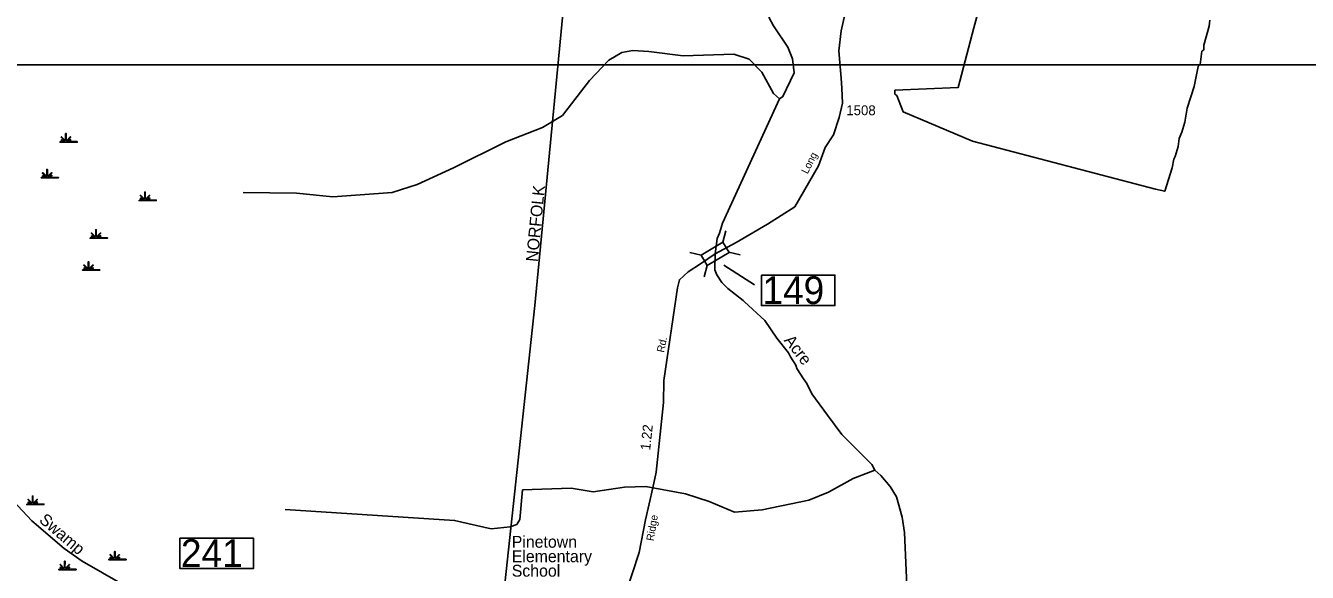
# Model space of a CAD drawing. Extents: x 2532689 to 2764727, y 536648 to 732970.
# Drawn here: x 2628920 to 2645127, y 685924 to 692837 of the extents above; entities that cross this region are included whole.
import ezdxf

# ---------------------------------------------------------------- set-up
doc = ezdxf.new("R2010")
doc.units = 0
for name, color, linetype in [('Exist Cultural Educational Facility Elementary Label', 7, 'Continuous'), ('Exist Hydrographic Creek Single Shore', 7, 'Continuous'), ('Exist Hydrographic Creek Single Shore Label', 7, 'Continuous'), ('Exist Hydrographic Swamp CELL', 7, 'Continuous'), ('Exist Railroad Mainline', 7, 'Continuous'), ('Exist Railroad Mainline Label', 7, 'Continuous'), ('Exist Road Primary US Structure Culvert Number Label', 7, 'Continuous'), ('Exist Road Secondary Mileage Hundredths English Label', 7, 'Continuous'), ('Exist Road Secondary Structure Standard Bridge CELL', 7, 'Continuous'), ('Exist Road Secondary Structure Standard Bridge Number Label', 7, 'Continuous'), ('Exist Road Secondary Type 51 Attributed', 7, 'Continuous'), ('Exist Road Secondary Type 51 Label', 7, 'Continuous'), ('Exist Road Secondary Type 51 Number Label', 7, 'Continuous'), ('Map Preparation Inset Cut Line', 7, 'Continuous')]:
    doc.layers.add(name, color=color, linetype=linetype)

msp = doc.modelspace()

# ---------------------------------------------------------------- linework, layer by layer
at = {"layer": 'Exist Hydrographic Creek Single Shore'}
msp.add_line((2638009, 689346), (2637991, 689361), dxfattribs=at)
for points in [[(2643608, 691793), (2643578, 691617), (2643540, 691491), (2643508, 691408), (2643494, 691309), (2643455, 691182), (2643439, 691149), (2643416, 691039), (2643323, 690743), (2643205, 690768), (2640892, 691374), (2640017, 691746), (2639937, 691953), (2639912, 691971), (2639911, 692020), (2640710, 692053), (2640910, 692809), (2641766, 695944)], [(2638454, 691912), (2638495, 691940), (2638639, 692241), (2638618, 692418), (2638556, 692566), (2638376, 692835), (2638323, 692935), (2638323, 693335), (2638347, 693402), (2638352, 693527), (2638375, 693629), (2638364, 694135)], [(2643892, 692907), (2643885, 692832), (2643816, 692589), (2643817, 692530), (2643792, 692513), (2643771, 692347), (2643746, 692320), (2643694, 692069), (2643655, 691936), (2643608, 691793)], [(2631671, 690728), (2632346, 690719), (2632806, 690672), (2633554, 690729), (2633869, 690827), (2634331, 691039), (2634991, 691368), (2635454, 691548), (2635708, 691702), (2636049, 692143), (2636293, 692399), (2636458, 692495), (2636599, 692523), (2636799, 692508), (2637234, 692454), (2637875, 692476), (2638068, 692412), (2638230, 692248), (2638378, 691978), (2638454, 691912)], [(2637991, 689361), (2637799, 689515), (2637722, 689587), (2637662, 689687), (2637635, 689751), (2637640, 689951), (2637666, 690144), (2637692, 690213), (2637731, 690339), (2638454, 691912)], [(2639657, 687216), (2639622, 687290), (2639239, 687666), (2639058, 687911), (2638860, 688182), (2638799, 688314), (2638756, 688372), (2638670, 688503), (2638661, 688542), (2638592, 688651), (2638566, 688699), (2638420, 688887), (2638265, 689110), (2638009, 689346)], [(2630789, 684697), (2630782, 684989), (2630728, 685203), (2630606, 685451), (2630436, 685605), (2629635, 686065), (2629406, 686227), (2628999, 686575), (2628641, 686961), (2628342, 687313), (2628240, 687411), (2628103, 687566), (2628085, 687624), (2628042, 687688), (2628025, 687740), (2627921, 687936), (2627823, 688218), (2627821, 688293), (2627759, 688485), (2627713, 688716), (2627701, 688883), (2627653, 689100), (2627643, 689138)], [(2632200, 686717), (2634345, 686581), (2634806, 686475), (2635047, 686498), (2635130, 686531), (2635170, 686591), (2635203, 686967), (2635820, 686989), (2636096, 686944), (2636494, 687003), (2636761, 687010), (2637263, 686919), (2637565, 686820), (2637885, 686685), (2638234, 686715), (2638824, 686838), (2639071, 686937), (2639384, 687110), (2639657, 687216)], [(2640064, 685759), (2640033, 686430), (2640003, 686623), (2639931, 686879), (2639853, 687011), (2639733, 687150), (2639657, 687216)]]:
    msp.add_lwpolyline(points, dxfattribs=at)
at = {"layer": 'Exist Hydrographic Swamp CELL'}
for points in [[(2629355, 691370), (2629408, 691370), (2629410, 691374), (2629372, 691389), (2629374, 691394), (2629412, 691378), (2629414, 691381), (2629369, 691426), (2629374, 691431), (2629420, 691385), (2629426, 691388), (2629426, 691471), (2629433, 691471), (2629433, 691388), (2629440, 691385), (2629485, 691431), (2629490, 691426), (2629446, 691381), (2629448, 691378), (2629489, 691396), (2629491, 691391), (2629450, 691373), (2629452, 691370), (2629573, 691370), (2629573, 691363), (2629355, 691363)], [(2629117, 690918), (2629170, 690918), (2629172, 690921), (2629133, 690936), (2629136, 690941), (2629174, 690926), (2629176, 690929), (2629131, 690973), (2629136, 690978), (2629182, 690933), (2629188, 690935), (2629188, 691018), (2629195, 691018), (2629195, 690935), (2629202, 690933), (2629247, 690978), (2629252, 690973), (2629208, 690929), (2629210, 690925), (2629250, 690944), (2629253, 690939), (2629212, 690921), (2629214, 690918), (2629335, 690918), (2629335, 690911), (2629117, 690911)], [(2630355, 690632), (2630408, 690632), (2630410, 690635), (2630371, 690650), (2630374, 690656), (2630412, 690640), (2630414, 690643), (2630369, 690687), (2630374, 690692), (2630420, 690647), (2630426, 690649), (2630426, 690732), (2630433, 690732), (2630433, 690649), (2630439, 690647), (2630485, 690692), (2630490, 690687), (2630445, 690643), (2630447, 690639), (2630488, 690658), (2630491, 690653), (2630450, 690635), (2630451, 690632), (2630572, 690632), (2630572, 690625), (2630355, 690625)], [(2629736, 690155), (2629789, 690155), (2629791, 690159), (2629752, 690174), (2629755, 690179), (2629793, 690163), (2629795, 690166), (2629750, 690211), (2629755, 690216), (2629801, 690170), (2629807, 690173), (2629807, 690256), (2629814, 690256), (2629814, 690173), (2629820, 690170), (2629866, 690216), (2629871, 690211), (2629826, 690166), (2629828, 690163), (2629869, 690181), (2629872, 690176), (2629831, 690158), (2629832, 690155), (2629954, 690155), (2629954, 690148), (2629736, 690148)], [(2629641, 689750), (2629693, 689750), (2629695, 689754), (2629657, 689769), (2629660, 689774), (2629698, 689758), (2629699, 689761), (2629655, 689806), (2629660, 689811), (2629705, 689765), (2629712, 689768), (2629712, 689851), (2629719, 689851), (2629719, 689768), (2629725, 689765), (2629771, 689811), (2629776, 689806), (2629731, 689761), (2629733, 689758), (2629774, 689776), (2629777, 689771), (2629736, 689753), (2629737, 689750), (2629858, 689750), (2629858, 689743), (2629641, 689743)], [(2628934, 686788), (2628987, 686788), (2628989, 686792), (2628951, 686807), (2628954, 686812), (2628991, 686796), (2628993, 686799), (2628949, 686844), (2628954, 686849), (2628999, 686803), (2629005, 686806), (2629005, 686889), (2629013, 686889), (2629013, 686806), (2629019, 686803), (2629064, 686849), (2629069, 686844), (2629025, 686799), (2629027, 686796), (2629068, 686814), (2629070, 686809), (2629029, 686791), (2629031, 686788), (2629152, 686788), (2629152, 686781), (2628934, 686781)], [(2629340, 685964), (2629393, 685964), (2629395, 685968), (2629357, 685983), (2629360, 685988), (2629397, 685972), (2629399, 685975), (2629355, 686020), (2629360, 686025), (2629405, 685979), (2629411, 685982), (2629411, 686065), (2629419, 686065), (2629418, 685982), (2629425, 685979), (2629470, 686025), (2629475, 686020), (2629431, 685975), (2629433, 685972), (2629474, 685990), (2629476, 685985), (2629435, 685967), (2629437, 685964), (2629558, 685964), (2629558, 685957), (2629340, 685957)], [(2629973, 686089), (2630025, 686089), (2630027, 686093), (2629989, 686108), (2629992, 686113), (2630030, 686097), (2630031, 686100), (2629987, 686145), (2629992, 686150), (2630037, 686104), (2630044, 686107), (2630044, 686190), (2630051, 686190), (2630051, 686107), (2630057, 686104), (2630102, 686150), (2630108, 686145), (2630063, 686100), (2630065, 686097), (2630106, 686115), (2630108, 686110), (2630067, 686092), (2630069, 686089), (2630190, 686089), (2630190, 686082), (2629973, 686082)]]:
    msp.add_lwpolyline(points, close=True, dxfattribs=at)
at = {"layer": 'Exist Railroad Mainline'}
msp.add_lwpolyline([(2634874, 684802), (2635359, 689300), (2635898, 694917)], dxfattribs=at)
at = {"layer": 'Exist Road Primary US Structure Culvert Number Label'}
msp.add_line((2637747, 689809), (2638138, 689561), dxfattribs=at)
at = {"layer": 'Exist Road Secondary Structure Standard Bridge CELL'}
for p, q in [((2637738, 690099), (2637774, 690241)), ((2637318, 689970), (2637461, 689934)), ((2637813, 689972), (2637956, 689937)), ((2637502, 689662), (2637538, 689805))]:
    msp.add_line(p, q, dxfattribs=at)
msp.add_lwpolyline([(2637461, 689934), (2637738, 690099), (2637815, 689970), (2637538, 689805)], close=True, dxfattribs=at)
at = {"layer": 'Exist Road Secondary Structure Standard Bridge Number Label'}
for points in [[(2638224, 689682), (2639153, 689682), (2639153, 689298), (2638224, 689298)], [(2630872, 686357), (2631801, 686357), (2631801, 685973), (2630872, 685973)]]:
    msp.add_lwpolyline(points, close=True, dxfattribs=at)
at = {"layer": 'Exist Road Secondary Type 51 Attributed'}
for points in [[(2639495, 693925), (2639234, 692769), (2639201, 692518), (2639234, 692174), (2639239, 692047), (2639250, 691856), (2639207, 691676), (2639136, 691457), (2639032, 691294), (2638945, 691065), (2638645, 690546), (2638302, 690328), (2637903, 690094), (2637640, 689951)], [(2637640, 689951), (2637453, 689827), (2637297, 689726), (2637187, 689624), (2637164, 689523), (2636992, 688352), (2636985, 688071), (2636891, 687189), (2636852, 686994), (2636758, 686588), (2636680, 686174), (2636502, 685638), (2636260, 685232), (2635630, 684001)]]:
    msp.add_lwpolyline(points, dxfattribs=at)
at = {"layer": 'Map Preparation Inset Cut Line'}
msp.add_lwpolyline([(2625780, 692342), (2701222, 692342), (2701222, 670513), (2663418, 670513), (2663418, 648997), (2625780, 648997)], close=True, dxfattribs=at)

# ---------------------------------------------------------------- texts
at = {"layer": 'Exist Cultural Educational Facility Elementary Label'}
for s, p in [('Pinetown', (2635067, 686236)), ('Elementary', (2635067, 686053)), ('School', (2635067, 685870))]:
    msp.add_text(s, height=150, dxfattribs=at).set_placement(p)
at = {"layer": 'Exist Hydrographic Creek Single Shore Label'}
for s, rotation, p in [('Acre', 307.8652, (2638502, 688855)), ('Swamp', 319.4683, (2629080, 686570))]:
    msp.add_text(s, height=150, rotation=rotation, dxfattribs=at).set_placement(p)
at = {"layer": 'Exist Railroad Mainline Label'}
msp.add_text('NORFOLK', height=150, rotation=84.5279, dxfattribs=at).set_placement((2635395, 689845))
at = {"layer": 'Exist Road Secondary Mileage Hundredths English Label'}
msp.add_text('1.22', height=125, rotation=83.9411, dxfattribs=at).set_placement((2636817, 687463))
at = {"layer": 'Exist Road Secondary Structure Standard Bridge Number Label'}
for s, p in [('149', (2638237, 689317)), ('241', (2630884, 685993))]:
    msp.add_text(s, height=350, dxfattribs=at).set_placement(p)
at = {"layer": 'Exist Road Secondary Type 51 Label'}
for s, rotation, p in [('Long', 63.0627, (2638807, 690954)), ('Rd.', 77.4704, (2636991, 688698)), ('Ridge', 80.585, (2636861, 686316))]:
    msp.add_text(s, height=95, rotation=rotation, dxfattribs=at).set_placement(p)
at = {"layer": 'Exist Road Secondary Type 51 Number Label'}
msp.add_text('1508', height=125, dxfattribs=at).set_placement((2639297, 691704))

doc.saveas('drawing.dxf')
